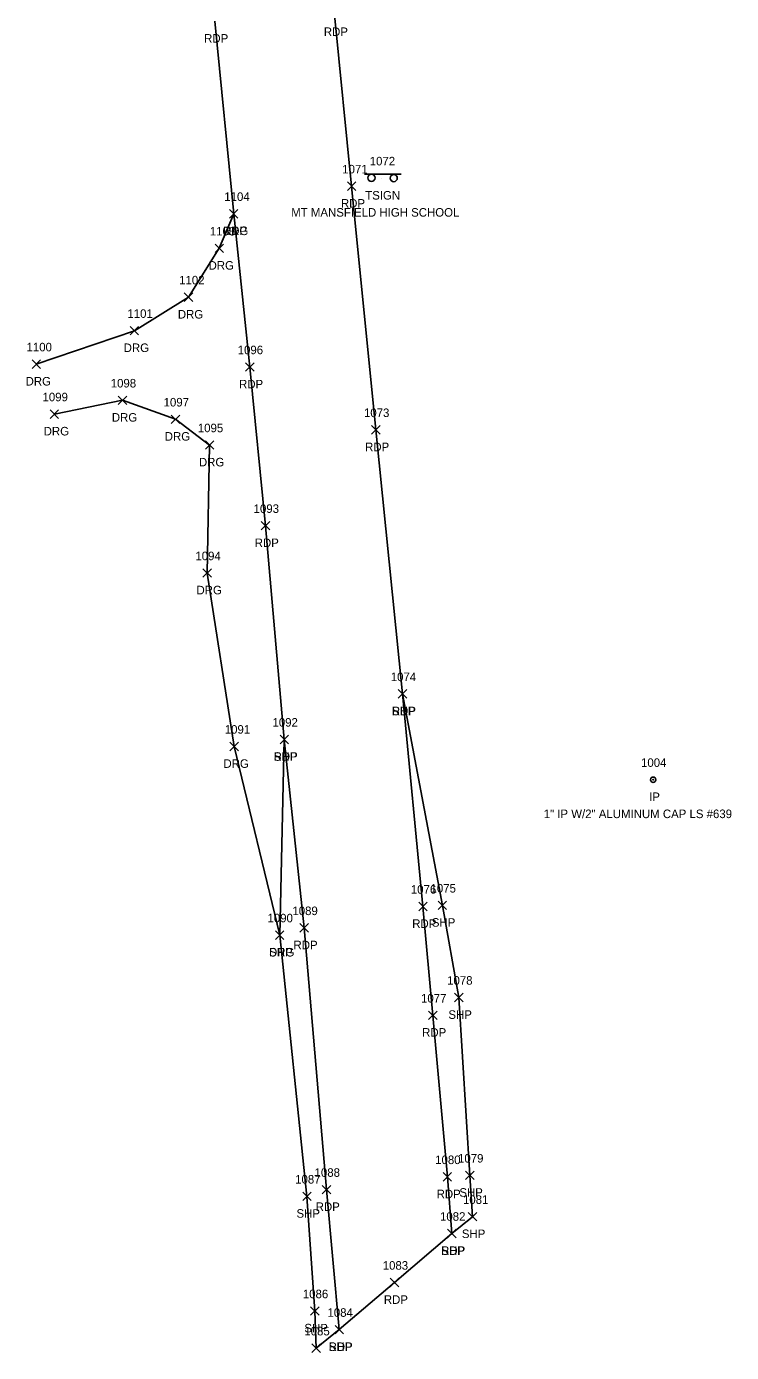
# Model space of a CAD drawing. Extents: x 1503463 to 1505240, y 712171 to 717196.
# Drawn here: x 1505074.8 to 1505239.9, y 713208 to 713518.5 of the extents above; entities that cross this region are included whole.
import ezdxf

# ---------------------------------------------------------------- set-up
doc = ezdxf.new("R2010")
doc.units = 0
for name, color, linetype in [('M_A', 7, 'Continuous'), ('M_C', 7, 'Continuous'), ('M_I', 7, 'Continuous'), ('MPIR', 7, 'Continuous'), ('P_A', 7, 'Continuous'), ('P_I', 7, 'Continuous'), ('P_TIC', 7, 'Continuous'), ('PET', 7, 'Continuous'), ('PSP', 7, 'Continuous'), ('R_A', 7, 'Continuous'), ('R_I', 7, 'Continuous'), ('R_TIC', 7, 'Continuous'), ('RDG', 7, 'Continuous'), ('S_A', 7, 'Continuous'), ('S_C', 7, 'Continuous'), ('S_I', 7, 'Continuous'), ('SSGN', 7, 'Continuous')]:
    doc.layers.add(name, color=color, linetype=linetype)

msp = doc.modelspace()

# ---------------------------------------------------------------- linework, layer by layer
at = {"layer": 'MPIR'}
for radius in [0.625, 0.0833]:
    msp.add_circle((1505221.61, 713342.14), radius, dxfattribs=at)
at = {"layer": 'P_TIC'}
for points in [[(1505149.98, 713480.09), (1505151.98, 713482.09)], [(1505151.98, 713480.09), (1505149.98, 713482.09)], [(1505122.35, 713473.65), (1505124.35, 713475.65)], [(1505124.35, 713473.65), (1505122.35, 713475.65)], [(1505126.12, 713437.76), (1505128.12, 713439.76)], [(1505128.12, 713437.76), (1505126.12, 713439.76)], [(1505155.64, 713423.05), (1505157.64, 713425.05)], [(1505157.64, 713423.05), (1505155.64, 713425.05)], [(1505129.79, 713400.6), (1505131.79, 713402.6)], [(1505131.79, 713400.6), (1505129.79, 713402.6)], [(1505161.91, 713361.22), (1505163.91, 713363.22)], [(1505163.91, 713361.22), (1505161.91, 713363.22)], [(1505161.91, 713361.22), (1505163.91, 713363.22)], [(1505163.91, 713361.22), (1505161.91, 713363.22)], [(1505134.21, 713350.56), (1505136.21, 713352.56)], [(1505136.21, 713350.56), (1505134.21, 713352.56)], [(1505134.21, 713350.56), (1505136.21, 713352.56)], [(1505136.21, 713350.56), (1505134.21, 713352.56)], [(1505166.68, 713311.44), (1505168.68, 713313.44)], [(1505168.68, 713311.44), (1505166.68, 713313.44)], [(1505171.23, 713311.71), (1505173.23, 713313.71)], [(1505173.23, 713311.71), (1505171.23, 713313.71)], [(1505138.88, 713306.43), (1505140.88, 713308.43)], [(1505140.88, 713306.43), (1505138.88, 713308.43)], [(1505133.13, 713304.74), (1505135.13, 713306.74)], [(1505135.13, 713304.74), (1505133.13, 713306.74)], [(1505175.11, 713290.13), (1505177.11, 713292.13)], [(1505177.11, 713290.13), (1505175.11, 713292.13)], [(1505169, 713285.96), (1505171, 713287.96)], [(1505171, 713285.96), (1505169, 713287.96)], [(1505172.4, 713248.13), (1505174.4, 713250.13)], [(1505174.4, 713248.13), (1505172.4, 713250.13)], [(1505177.68, 713248.49), (1505179.68, 713250.49)], [(1505179.68, 713248.49), (1505177.68, 713250.49)], [(1505139.52, 713243.57), (1505141.52, 713245.57)], [(1505141.52, 713243.57), (1505139.52, 713245.57)], [(1505144.07, 713245.15), (1505146.07, 713247.15)], [(1505146.07, 713245.15), (1505144.07, 713247.15)], [(1505178.27, 713238.81), (1505180.27, 713240.81)], [(1505180.27, 713238.81), (1505178.27, 713240.81)], [(1505173.45, 713234.86), (1505175.45, 713236.86)], [(1505175.45, 713234.86), (1505173.45, 713236.86)], [(1505173.45, 713234.86), (1505175.45, 713236.86)], [(1505175.45, 713234.86), (1505173.45, 713236.86)], [(1505160.03, 713223.4), (1505162.03, 713225.4)], [(1505162.03, 713223.4), (1505160.03, 713225.4)], [(1505141.37, 713216.72), (1505143.37, 713218.72)], [(1505143.37, 713216.72), (1505141.37, 713218.72)], [(1505147.09, 713212.37), (1505149.09, 713214.37)], [(1505149.09, 713212.37), (1505147.09, 713214.37)], [(1505147.09, 713212.37), (1505149.09, 713214.37)], [(1505149.09, 713212.37), (1505147.09, 713214.37)], [(1505141.67, 713208.02), (1505143.67, 713210.02)], [(1505143.67, 713208.02), (1505141.67, 713210.02)]]:
    msp.add_lwpolyline(points, dxfattribs=at)
at = {"layer": 'PET'}
msp.add_lwpolyline([(1505146.98, 713521.26), (1505150.98, 713481.09), (1505156.64, 713424.05), (1505162.91, 713362.22), (1505167.68, 713312.44), (1505170, 713286.96), (1505173.4, 713249.13), (1505174.45, 713235.86), (1505161.03, 713224.4), (1505148.09, 713213.37), (1505145.07, 713246.15), (1505139.88, 713307.43), (1505135.21, 713351.56), (1505130.79, 713401.6), (1505127.12, 713438.76), (1505123.35, 713474.65), (1505118.94, 713519.71)], dxfattribs=at)
at = {"layer": 'PSP'}
for points in [[(1505162.91, 713362.22), (1505172.23, 713312.71), (1505176.11, 713291.13), (1505178.68, 713249.49), (1505179.27, 713239.81), (1505174.45, 713235.86)], [(1505148.09, 713213.37), (1505142.67, 713209.02), (1505142.37, 713217.72), (1505140.52, 713244.57), (1505134.13, 713305.74), (1505135.21, 713351.56)]]:
    msp.add_lwpolyline(points, dxfattribs=at)
at = {"layer": 'R_TIC'}
for points in [[(1505122.35, 713473.65), (1505124.35, 713475.65)], [(1505124.35, 713473.65), (1505122.35, 713475.65)], [(1505118.98, 713465.56), (1505120.98, 713467.56)], [(1505120.98, 713465.56), (1505118.98, 713467.56)], [(1505111.79, 713454.11), (1505113.79, 713456.11)], [(1505113.79, 713454.11), (1505111.79, 713456.11)], [(1505099.09, 713446.27), (1505101.09, 713448.27)], [(1505101.09, 713446.27), (1505099.09, 713448.27)], [(1505076.12, 713438.43), (1505078.12, 713440.43)], [(1505078.12, 713438.43), (1505076.12, 713440.43)], [(1505096.33, 713429.97), (1505098.33, 713431.97)], [(1505098.33, 713429.97), (1505096.33, 713431.97)], [(1505080.35, 713426.74), (1505082.35, 713428.74)], [(1505082.35, 713426.74), (1505080.35, 713428.74)], [(1505108.71, 713425.52), (1505110.71, 713427.52)], [(1505110.71, 713425.52), (1505108.71, 713427.52)], [(1505116.72, 713419.49), (1505118.72, 713421.49)], [(1505118.72, 713419.49), (1505116.72, 713421.49)], [(1505116.15, 713389.53), (1505118.15, 713391.53)], [(1505118.15, 713389.53), (1505116.15, 713391.53)], [(1505122.46, 713348.91), (1505124.46, 713350.91)], [(1505124.46, 713348.91), (1505122.46, 713350.91)], [(1505133.13, 713304.74), (1505135.13, 713306.74)], [(1505135.13, 713304.74), (1505133.13, 713306.74)]]:
    msp.add_lwpolyline(points, dxfattribs=at)
at = {"layer": 'RDG'}
for points in [[(1505077.12, 713439.43), (1505100.09, 713447.27), (1505112.79, 713455.11), (1505119.98, 713466.56), (1505123.35, 713474.65)], [(1505134.13, 713305.74), (1505123.46, 713349.91), (1505117.15, 713390.53), (1505117.72, 713420.49), (1505109.71, 713426.52), (1505097.33, 713430.97), (1505081.35, 713427.74)]]:
    msp.add_lwpolyline(points, dxfattribs=at)
at = {"layer": 'SSGN'}
for p, q in [((1505153.96, 713483.9), (1505162.56, 713483.9)), ((1505157.98, 713482.99), (1505157.98, 713482.99))]:
    msp.add_line(p, q, dxfattribs=at)
for centre in [(1505155.62, 713483.06), (1505160.84, 713482.99)]:
    msp.add_circle(centre, 0.833, dxfattribs=at)

# ---------------------------------------------------------------- texts
at = {"layer": 'M_A'}
msp.add_text('IP', height=2, dxfattribs=at).set_placement((1505220.66, 713337.14))
at = {"layer": 'M_C'}
msp.add_text('1" IP W/2" ALUMINUM CAP LS #639', height=2, dxfattribs=at).set_placement((1505195.97, 713333.14))
at = {"layer": 'M_I'}
msp.add_text('1004', height=2, dxfattribs=at).set_placement((1505218.76, 713345.14))
at = {"layer": 'P_A'}
for s, p in [('RDP', (1505144.47, 713516.26)), ('RDP', (1505116.43, 713514.71)), ('RDP', (1505148.47, 713476.09)), ('RDP', (1505120.84, 713469.65)), ('RDP', (1505124.61, 713433.76)), ('RDP', (1505154.13, 713419.05)), ('RDP', (1505128.28, 713396.6)), ('SHP', (1505160.44, 713357.22)), ('RDP', (1505160.4, 713357.22)), ('SHP', (1505132.75, 713346.56)), ('RDP', (1505132.7, 713346.56)), ('RDP', (1505165.17, 713307.44)), ('SHP', (1505169.77, 713307.71)), ('RDP', (1505137.36, 713302.43)), ('SHP', (1505131.66, 713300.74)), ('SHP', (1505173.65, 713286.13)), ('RDP', (1505167.49, 713281.96)), ('RDP', (1505170.89, 713244.13)), ('SHP', (1505176.21, 713244.49)), ('RDP', (1505142.56, 713241.15)), ('SHP', (1505138.06, 713239.57)), ('SHP', (1505176.8, 713234.81)), ('SHP', (1505171.99, 713230.86)), ('RDP', (1505171.94, 713230.86)), ('RDP', (1505158.52, 713219.4)), ('SHP', (1505139.91, 713212.72)), ('SHP', (1505145.63, 713208.37)), ('RDP', (1505145.58, 713208.37))]:
    msp.add_text(s, height=2, dxfattribs=at).set_placement(p)
at = {"layer": 'P_I'}
for s, p in [('1071', (1505148.78, 713484.09)), ('1104', (1505121.15, 713477.65)), ('1096', (1505124.29, 713441.76)), ('1073', (1505153.87, 713427.05)), ('1093', (1505128.02, 713404.6)), ('1074', (1505160.14, 713365.22)), ('1074', (1505160.14, 713365.22)), ('1092', (1505132.44, 713354.56)), ('1092', (1505132.44, 713354.56)), ('1076', (1505164.85, 713315.44)), ('1075', (1505169.46, 713315.71)), ('1090', (1505131.27, 713308.74)), ('1089', (1505137.1, 713310.43)), ('1078', (1505173.34, 713294.13)), ('1077', (1505167.23, 713289.96)), ('1079', (1505175.9, 713252.49)), ('1080', (1505170.55, 713252.13)), ('1087', (1505137.75, 713247.57)), ('1088', (1505142.3, 713249.15)), ('1081', (1505177.06, 713242.81)), ('1082', (1505171.68, 713238.86)), ('1082', (1505171.68, 713238.86)), ('1083', (1505158.26, 713227.4)), ('1086', (1505139.55, 713220.72)), ('1084', (1505145.32, 713216.37)), ('1084', (1505145.32, 713216.37)), ('1085', (1505139.9, 713212.02))]:
    msp.add_text(s, height=2, dxfattribs=at).set_placement(p)
at = {"layer": 'R_A'}
for p in [(1505120.84, 713469.65), (1505117.47, 713461.56), (1505110.27, 713450.11), (1505097.58, 713442.27), (1505074.61, 713434.43), (1505094.81, 713425.97), (1505078.84, 713422.74), (1505107.2, 713421.52), (1505115.21, 713415.49), (1505114.64, 713385.53), (1505120.95, 713344.91), (1505131.62, 713300.74)]:
    msp.add_text('DRG', height=2, dxfattribs=at).set_placement(p)
at = {"layer": 'R_I'}
for s, p in [('1104', (1505121.15, 713477.65)), ('1103', (1505117.78, 713469.56)), ('1102', (1505110.58, 713458.11)), ('1101', (1505098.45, 713450.27)), ('1100', (1505074.83, 713442.43)), ('1098', (1505094.55, 713433.97)), ('1099', (1505078.57, 713430.74)), ('1097', (1505106.94, 713429.52)), ('1095', (1505114.95, 713423.49)), ('1094', (1505114.38, 713393.53)), ('1091', (1505121.26, 713352.91)), ('1090', (1505131.27, 713308.74))]:
    msp.add_text(s, height=2, dxfattribs=at).set_placement(p)
at = {"layer": 'S_A'}
msp.add_text('TSIGN', height=2, dxfattribs=at).set_placement((1505154.16, 713477.97))
at = {"layer": 'S_C'}
msp.add_text('MT MANSFIELD HIGH SCHOOL', height=2, dxfattribs=at).set_placement((1505136.83, 713473.97))
at = {"layer": 'S_I'}
msp.add_text('1072', height=2, dxfattribs=at).set_placement((1505155.21, 713485.97))

doc.saveas('drawing.dxf')
